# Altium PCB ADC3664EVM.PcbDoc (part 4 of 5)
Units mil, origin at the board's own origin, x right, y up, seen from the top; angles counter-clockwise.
Board outline 3900 x 2716.54 mil, 10 copper layers (Top Layer, L2 GND, L3 PWR, L4 GND, L5 SIG, L6 GND, L7 GND, L8 PWR, L9 GND, Bottom Layer), stack 61.2 mil thick; 332 components, 223 nets, 1425 pads, 969 vias.
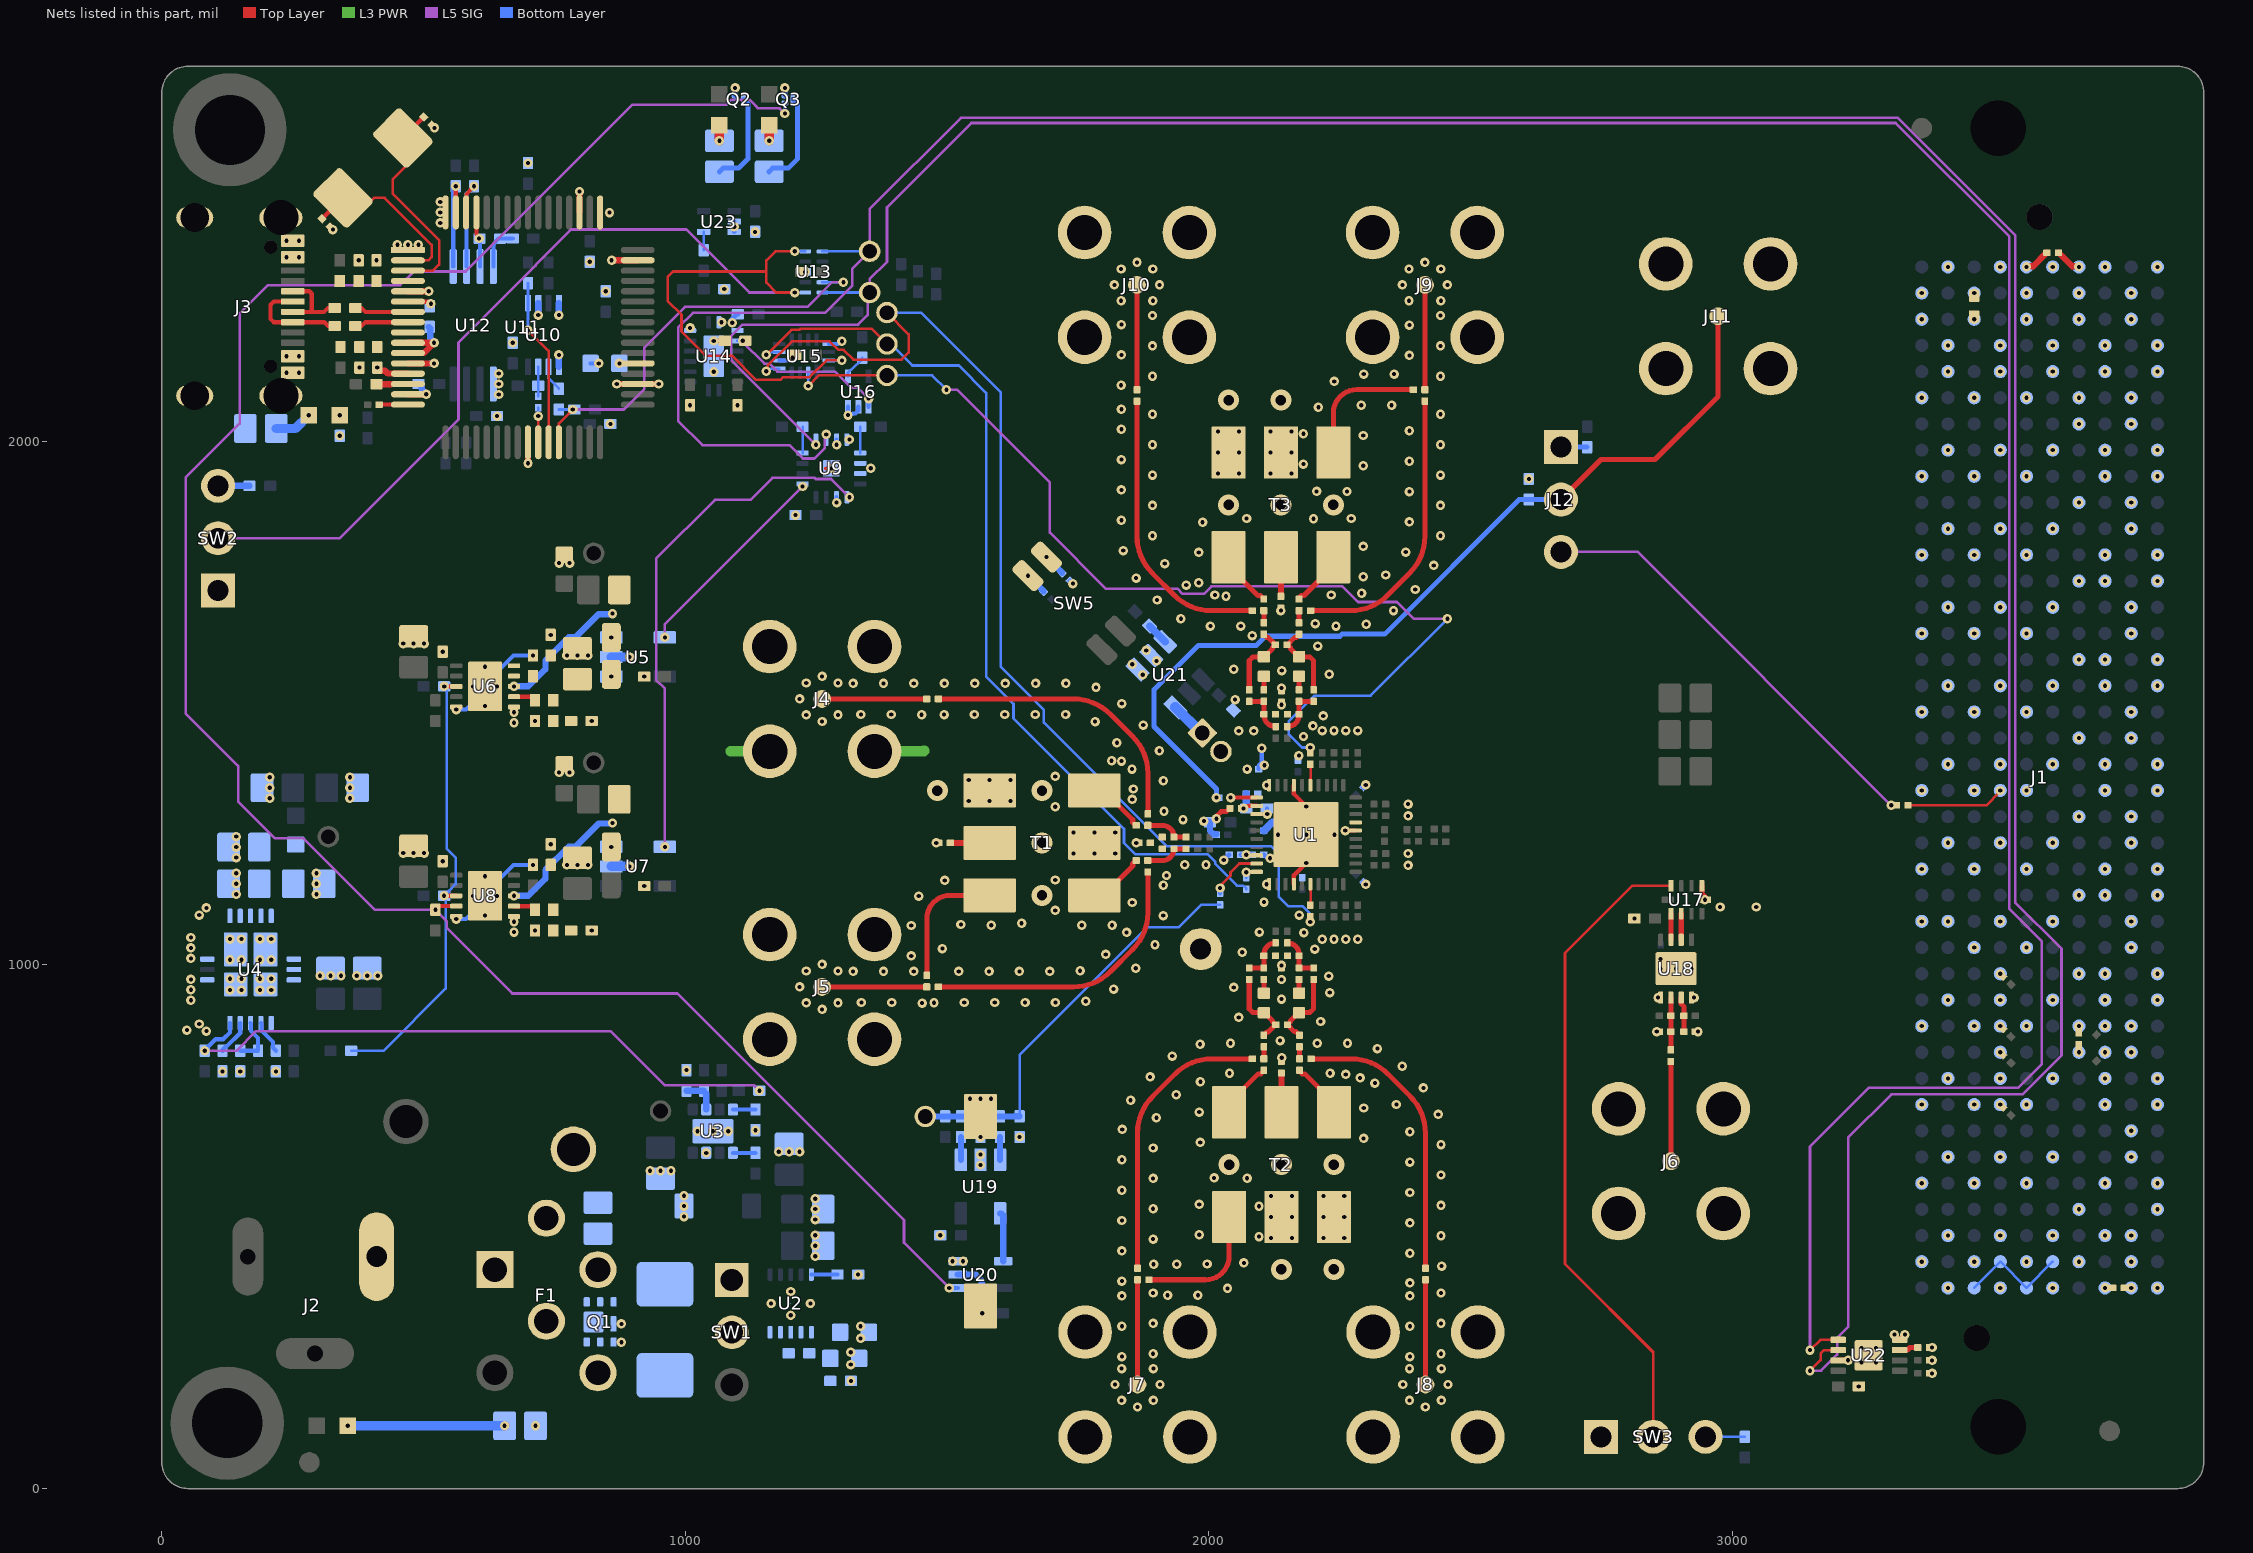
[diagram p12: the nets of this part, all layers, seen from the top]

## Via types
v1: diameter 18, hole 8, Top Layer to Bottom Layer, tented both sides, 952 vias
v2: diameter 40, hole 20, Top Layer to Bottom Layer, tented both sides, 14 vias
v3: diameter 18, hole 8, Top Layer to Bottom Layer, tented bottom, 3 vias

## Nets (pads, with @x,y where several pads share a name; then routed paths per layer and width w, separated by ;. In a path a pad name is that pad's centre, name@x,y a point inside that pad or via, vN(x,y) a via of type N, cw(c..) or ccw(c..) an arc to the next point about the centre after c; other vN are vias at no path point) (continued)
GND: C2.1 C3.1 C4.1 C5.1 C6.1 C7.1 C8.1 C9.1 C10.1 C11.1 C12.1 C13.1 C14.1 C15.1 C16.2 C17.1 C18.1 C19.1 C20.1 C21.1 C22.1 C23.1 C24.1 C25.1 C26.1 C27.1 C28.1 C29.1 C30.1 C31.1 C32.1 C33.1 C34.1 C35.1 C36.1 C37.1 C38.1 C39.1 C40.1 C41.1 C42.1 C43.1 C44.1 C45.1 C46.1 C47.1 C50.2 C51.1 C55.1 C56.1 C61.1 C62.2 C69.1 C70.2 C74.1 C75.1 C76.1 C77.1 C78.1 C79.1 C80.1 C81.1 C82.1 C83.1 C84.1 C85.1 C86.1 C87.1 C88.1 C89.1 D3.2 J1.A1 J1.A4 J1.A5 J1.A8 J1.A9 J1.A12 J1.A13 J1.A16 J1.A17 J1.A20 J1.A21 J1.A24 J1.A25 J1.A28 J1.A29 J1.A32 J1.A33 J1.A36 J1.A37 J1.A40 J1.B2 J1.B3 J1.B6 J1.B7 J1.B10 J1.B11 J1.B14 J1.B15 J1.B18 J1.B19 J1.B22 J1.B23 J1.B26 J1.B27 J1.B30 J1.B31 J1.B34 J1.B35 J1.B38 J1.B39 J1.C1 J1.C4 J1.C5 J1.C8 J1.C9 J1.C12 J1.C13 J1.C16 J1.C17 J1.C20 J1.C21 J1.C24 J1.C25 J1.C28 J1.C29 J1.C32 J1.C33 J1.C36 J1.C38 J1.C40 J1.D2 J1.D3 J1.D6 J1.D7 J1.D10 J1.D13 J1.D16 J1.D19 J1.D22 J1.D25 J1.D28 J1.D37 J1.D39 J1.E1 J1.E4 J1.E5 J1.E8 J1.E11 J1.E14 J1.E17 J1.E20 J1.E23 J1.E26 J1.E29 J1.E32 J1.E35 J1.E38 J1.E40 J1.F2 J1.F3 J1.F6 J1.F9 J1.F12 J1.F15 J1.F18 J1.F21 J1.F24 J1.F27 J1.F30 J1.F33 J1.F36 J1.F39 J1.G1 J1.G4 J1.G5 J1.G8 J1.G11 J1.G14 J1.G17 J1.G20 J1.G23 J1.G26 J1.G29 J1.G32 J1.G35 J1.G38 J1.G40 J1.H3 J1.H6 J1.H9 J1.H12 J1.H15 J1.H18 J1.H21 J1.H24 J1.H27 J1.H30 J1.H33 J1.H36 J1.H39 J1.J1 J1.J4 J1.J5 J1.J8 J1.J11 J1.J14 J1.J17 J1.J20 J1.J23 J1.J26 J1.J29 J1.J32 J1.J35 J1.J38 J1.J40 J1.K2 J1.K3 J1.K6 J1.K9 J1.K12 J1.K15 J1.K18 J1.K21 J1.K24 J1.K26 J1.K30 J1.K33 J1.K36 J1.K39 J3.1 J3.2 J3.3 J3.4 J3.A1 J3.B1 J4.2 J4.3 J4.4 J4.5 J5.2 J5.3 J5.4 J5.5 J6.2 J6.3 J6.4 J6.5 J7.2 J7.3 J7.4 J7.5 J8.2 J8.3 J8.4 J8.5 J9.2 J9.3 J9.4 J9.5 J10.2 J10.3 J10.4 J10.5 J11.2 J11.3 J11.4 J11.5 Q1.4 Q1.7 Q2.2@1095,2660 Q3.2@1190,2660 R2.1 R3.1 R4.1 R8.1 R13.1 R14.1 R20.1 R22.1 R29.1 R31.1 R45.1 R46.1 R55.1 R58.2 R73.1 R74.1 R106.1 R125.1 R132.1 R133.1 R134.1 R135.1 R136.1 R137.1 R146.1 R147.1 R150.2 SW2.3 SW3.3 SW4.2 T1.1 T1.5 T2.2 T2.3 T3.2 T3.3 U1.3 U1.11 U1.14 U1.26 U1.37 U1.40 U1.41 U2.11 U3.3 U3.9 U4.1 U4.2 U4.3 U4.5 U4.6 U4.7 U4.8 U4.9 U4.16 U4.17 U4.20 U4.25 U4.26 U4.28 U5.2 U6.6 U6.11 U7.2 U8.6 U8.11 U9.2 U9.3 U9.6 U9.15 U9.16 U9.17 U10.2 U10.4 U10.5 U11.1 U11.5 U11.10 U11.11 U11.13 U11.15 U11.25 U11.35 U11.47 U11.51 U12.5 U13.3@1228.98,2323.6 U14.7 U14.9 U14.10 U14.17 U15.6 U15.13 U16.2 U16.3 U17.5 U17.6 U18.1 U18.4 U18.9 U19.2 U20.3 U21.1 U21.2 U22.4 U22.7 U22.9 U23.2 U23.3 | length 1947.6
  Top Layer w8: v1(460.98,1213.72) 474.98,1227.72 C24.1@480.98,1227.72 ; v1(460.98,1613.72) 474.98,1627.72 C18.1@480.98,1627.72 ; v1(480.98,1213.72) C24.1@480.98,1227.72 ; v1(480.98,1613.72) C18.1@480.98,1627.72 ; v1(500.98,1213.72) 486.98,1227.72 C24.1@480.98,1227.72 ; v1(500.98,1613.72) 486.98,1627.72 C18.1@480.98,1627.72 ; v1(758.74,1367.62) 758.74,1373.36 C27.1@768.74,1383.36 778.74,1373.36 v1(778.74,1367.62) ; v1(758.74,1767.62) 758.74,1773.36 C21.1@768.74,1783.36 778.74,1773.36 v1(778.74,1767.62) ; v1(773.72,1191.03) 787.72,1205.03 C26.1@793.72,1205.03 ; v1(773.72,1591.03) 787.72,1605.03 C20.1@793.72,1605.03 ; v1(793.72,1191.03) C26.1@793.72,1205.03 ; v1(793.72,1591.03) C20.1@793.72,1605.03 ; v1(813.72,1191.03) 799.72,1205.03 C26.1@793.72,1205.03 ; v1(813.72,1591.03) 799.72,1605.03 C20.1@793.72,1605.03 ; v1(1479.06,1233.05) C50.2@1484.06,1233.05 ; v1(1861.06,1233.05) C51.1@1866.06,1233.05 ; U1.3@2091.2,1288.17 v1(2111.2,1288.17) ; v1(2109.82,1154.31) U1.11@2114.82,1154.31 ; v1(2109.82,1343.29) U1.40@2114.82,1343.29 ; v1(2137.46,1676.83) C70.2@2137.46,1681.83 ; C69.1@2138.45,1523.99 v1(2138.45,1528.99) ; U1.14@2162.07,1154.31 2162.07,1171.24 U1.41@2185.69,1194.86 ; U1.37@2162.07,1343.29 2162.07,1326.36 U1.41@2185.69,1302.73 ; v1(2260.18,1256.67) U1.26@2280.18,1256.67 ; v1(2857.58,937.74) U18.1@2862.58,937.74 ; U18.4@2921.64,937.74 v1(2926.64,937.74) ; 1269.05,1948.3 U9.17@1278.9,1948.29 1269.05,1948.29
  Top Layer w9: U14.17@1054.25,2192.04 R55.1@1075.16,2192.04 ; v1@2015,1285 2022.99,1292.99 2033.44,1292.99 2039.37,1298.92 C85.1@2040.16,1298.92
  Top Layer w9.7: U17.6@2941.32,1151.13 2941.32,1136.36 2947.23,1130.46 v1(2947.23,1124.55)
  Top Layer w10: U22.7@3201.8,244.68 3202.01,244.88 3220.36,244.88 v1(3220.57,245.09) ; v1(3309.06,294.05) U22.4@3319.06,284.05 v1(3329.06,294.05) ; R134.1@3376.1,219.99 v1(3381.1,219.99) ; R135.1@3376.1,244.68 v1(3381.1,244.68) ; R136.1@3376.1,269.36 v1(3381.1,269.36) ; v1(3461.42,2233.27) R146.1@3461.42,2238.58 ; v1(3711.42,383.27) R137.1@3726.08,383.27
  Top Layer w12: C42.1@321.7,2409.56 v1(326.7,2404.56) ; v1(411.37,2140.87) 411.37,2138.91 415.21,2135.06 426.33,2135.06 431.82,2129.57 469.65,2129.57 U11.13@470,2129.23 ; U11.15@470,2089.86 v1(505,2089.86) ; U11.11@470,2168.6 500.32,2168.6 v1(520,2188.28) U11.10@470,2188.28 ; U11.5@470,2286.71 v1(510,2286.71) ; C43.1@515.84,2603.7 v1(520.84,2598.7) ; v1(699.33,1958.32) U11.25@699.33,1998.32 ; U11.51@797.76,2437.3 v1(797.76,2477.3) ; v1(858.98,2345.76) U11.47@908.98,2345.76 ; v1(868.98,2109.54) U11.35@908.98,2109.54 v1(948.98,2109.54)
  L3 PWR w20: 1086.21,1408.05 J4.4@1161.11,1408.05 ; J4.5@1361.11,1408.05 1454.85,1408.05 1455.97,1409.17
  Bottom Layer w5: U14.7@1008.98,2211.73 v1(1008.98,2216.73) ; U14.9@1064.09,2227.47 v1(1069.09,2227.47)
  Bottom Layer w8: C35.1@818.86,2148.91 v1(834.61,2148.91) ; U23.3@1093.18,2400.12 v1(1093.18,2409.96) U23.2@1093.18,2419.8 ; U15.6@1179.53,2154.64 1196.82,2154.64 1201.82,2159.64 v1(1204.53,2159.64) ; U15.13@1274.02,2186.14 1291.31,2186.14 1296.31,2191.14 v1(1299.02,2191.14) ; v1(1288.74,1883.18) U9.6@1288.74,1893.18 ; v1(1288.74,1993.41) U9.15@1288.74,2003.41 ; U16.3@1310.63,2065.97 1310.63,2052.78 v1(1310.63,2050.22) 1312.54,2052.13 1319.1,2052.13 1320.32,2053.35 1324.98,2053.35 1330.32,2058.68 U16.2@1330.32,2065.97 ; v1(2028.18,1200.25) 2028.18,1200.67 2037.94,1210.43 C79.1@2038.72,1210.43 ; R132.1@2094.77,1374.15 2094.77,1380.45 2100.76,1386.44 v1(2100.76,1413.81) ; C80.1@2104.53,1210.43 2105.32,1210.43 2111.25,1204.5 2116.05,1204.5 v1(2116.62,1203.93) ; C83.1@2110.57,1298.92 2110.57,1289.07 2111.2,1289.07 v1(2111.2,1288.17)
  Bottom Layer w9: v1(1089.53,2226.73) 1089.05,2227.2 1089.05,2233.76 1098.32,2243.02 R58.2@1100.29,2243.02
  Bottom Layer w9.7: Q2.2@1095,2660 v1(1095,2675) ; Q3.2@1190,2660 v1(1190,2675) ; R133.1@1735.07,1733.29 v1(1740.07,1728.29)
  Bottom Layer w12: C37.1@490.24,2109.54 492.21,2109.54 496.06,2105.7 496.06,2099.89 505,2090.94 v1(505,2089.86) ; R46.1@510,2218.61 512.81,2215.81 512.81,2197.1 520,2189.9 v1(520,2188.28) v1@512,2188.28 ; v1(719.02,2241.27) U10.2@719.02,2264.27 ; U10.5@758.39,2142.22 v1(758.39,2165.22) ; v1(758.39,2241.27) U10.4@758.39,2264.27 ; v1@1313.15,2002.7 v1(1313.15,2003.55) ; v1(1990.19,1274.7) 1991.33,1273.56 2000.69,1273.56 C87.1@2001.83,1272.42 2001.83,1256.45 2008.86,1249.42 C88.1@2014.16,1249.42 ; C77.1@2295.77,1157.34 v1(2299.3,1153.81) ; C78.1@2295.77,1340.25 v1(2299.3,1343.79)
  Bottom Layer w15: C75.1@2104.53,1256.67 2105.32,1256.67 2121.07,1272.42 2126.64,1272.42
  Bottom Layer w18: U7.2@858.46,1188.15 v1(893.46,1188.15) ; U5.2@858.46,1588.15 v1(893.46,1588.15)
  other v1: 713.73,119.85 1863.45,155.72 2413.45,155.72 1833.04,168.31 1893.85,168.31 2383.04,168.31 2443.85,168.31 3241.17,194.99 1820.45,198.72 1906.45,198.72 2370.45,198.72 2456.45,198.72 1316.31,205.62 1833.04,229.13 1893.85,229.13 2383.04,229.13 2443.85,229.13 1315.9,236.67 1833.73,251.91 2383.73,251.91 1893.17,257.52 2443.17,257.52 1315.9,260.14 877.82,279.42 1334.68,286.67 1334.68,310.14 1833.73,309.91 2383.73,309.91 877.82,314.42 1893.17,315.52 2443.17,315.52 1833.73,367.91 2383.73,367.91 1920.88,369 1978.88,369 1893.17,373.52 2443.17,373.52 2035.36,382.2 3411.42,383.27 3511.42,383.27 3611.42,383.27 3811.42,383.27 2383.73,392.76 1833.72,396.3 1329.96,408.64 2444.32,424.84 1894.32,428.42 1938.51,428.44 1996.5,428.81 2066.73,430.98 3361.42,433.27 3461.42,433.27 3561.42,433.27 3661.42,433.27 3761.42,433.27 1510.3,434.23 1530.3,434.23 1248.09,443.64 2383.73,449.44 1833.73,453.87 1248.09,463.64 1893.17,476.41 2118.45,478.72 2158.45,478.72 2218.45,478.72 2258.45,478.72 2095.58,481.3 2443.17,482.83 1248.09,483.64 1486.89,483.65 3411.42,483.27 3511.42,483.27 3611.42,483.27 3711.42,483.27 3761.42,483.27 1981.32,484.79 2383.73,507.44 1833.73,511.87 1248.09,513.64 2118.45,518.72 2158.45,518.72 2218.45,518.72 2258.45,518.72 997.3,519.36 1248.09,533.64 3661.42,533.27 3811.42,533.27 1893.17,534.41 997.3,539.36 2095.58,539.3 2443.17,540.83 1981.32,542.79 1248.09,553.64 2118.45,558.72 2158.45,558.72 2218.45,558.72 2258.45,558.72 997.3,559.36 2383.73,565.44 1833.73,569.87 3361.42,583.27 3461.42,583.27 3561.42,583.27 3711.42,583.27 3811.42,583.27 1893.17,592.41 2072.72,592.61 2009.73,593.35 2443.17,598.83 932.5,606.94 952.5,606.94 972.5,606.94 1563.61,617.87 2383.73,623.44 1833.73,627.87 3411.42,633.27 3511.42,633.27 3611.42,633.27 3761.42,633.27 1563.61,637.87 1039.7,641.15 1178.13,643.42 1198.13,643.42 1218.13,643.42 1893.17,650.41 2443.17,656.83 1983.29,661.04 2295.21,668.82 1563.61,671.34 1638.32,671.43 2383.69,681.44 3761.42,683.27 1133.88,684.46 1834.29,685.87 1899.57,708.05 2437.83,714.58 1981.32,719.01 2295.58,726.82 2358.06,733.47 3361.42,733.27 3461.42,733.27 3561.42,733.27 3711.42,733.27 3811.42,733.27 1850.33,741.61 1543.61,744.61 1563.61,744.61 1583.61,744.61 1937.39,752.02 2409.59,765.24 2316.86,774.3 1983.52,776.97 3411.42,783.27 3511.42,783.27 3611.42,783.27 3711.42,783.27 3811.42,783.27 2288.58,784.39 1887.47,786.16 2261.33,791.05 2039.16,793.35 2231.27,793.35 115.89,796.75 149.89,796.75 217.89,796.75 1002.1,799.2 2368.96,806.63 2138.87,822.85 1929.7,825.92 3761.42,833.27 2321.72,840.29 1983.09,848.57 2041.06,850.49 2206.62,850.49 2264.62,850.49 2135.87,855.52 2855.22,872.74 2934,872.74 85.27,873.58 47.89,875.49 3361.42,883.27 3461.42,883.27 3561.42,883.27 3761.42,883.27 71.55,887.3 2213.26,892 2056.72,899.9 1261.11,915.05 1230.7,927.64 1291.51,927.64 1452.07,927.18 1474.77,927.69 1336.09,928.33 1394.09,928.33 1532.76,928.33 1590.76,928.33 1648.76,928.33 1706.76,928.33 1764.71,930.73 55.51,932.48 3411.42,933.27 3511.42,933.27 3611.42,933.27 3711.42,933.27 3811.42,933.27 2138.45,934.79 2230.67,947.33 55.51,952.48 1817.9,953.86 2047.21,957.11 1218.11,958.05 55.51,972.48 2138.45,972.22 2228.88,978.84 302.26,979.25 322.26,979.25 342.26,979.25 372.26,979.25 392.26,979.25 412.26,979.25 3661.42,983.27 3711.42,983.27 3811.42,983.27 1320.3,987.77 1378.3,987.77 1436.3,987.77 1521.96,987.77 1579.96,987.77 1637.96,987.77 1695.96,987.77 1230.7,988.46 1291.51,988.46 1753.95,988.8 1860.11,993.63 1261.11,1001.05 2862.58,1011.37 55.51,1012.48 1431.39,1017.35 1802.68,1020.26 2063.68,1024.29 2202.05,1030.26 1490.83,1031.32 55.51,1032.48 3461.42,1033.27 3561.42,1033.27 3761.42,1033.27 1896.97,1038.42 2216.16,1049.26 2238.76,1049.26 2261.36,1049.26 2283.96,1049.26 55.51,1052.48 2181.3,1061.83 672.72,1062.68 1842.66,1062.28 2096.27,1062.84 712.72,1065.91 821.09,1065.91 1431.39,1075.35 1584.19,1075.92 1757.05,1075.92 1815.05,1075.92 1526.21,1077.28 1642.06,1079.77 672.72,1082.68 3361.42,1083.27 3411.42,1083.27 3511.42,1083.27 3611.42,1083.27 3761.42,1083.27 2812.41,1088.72 1912.59,1094.28 71.55,1095.3 2172.52,1095.34 1706.48,1104.31 85.27,1109.02 2976.29,1110.64 3045.39,1110.64 1853.44,1119.27 2105.13,1120.16 1445.8,1131.53 3661.42,1133.27 3711.42,1133.27 3811.42,1133.27 142.26,1135 295.33,1135 921.46,1150.75 1912.87,1152.28 142.26,1155 295.33,1155 1495.39,1161.6 1706.48,1162.31 1918.93,1170.82 142.26,1175 295.33,1175 3361.42,1183.27 3461.42,1183.27 3561.42,1183.27 3711.42,1183.27 3811.42,1183.27 2380.23,1190.25 1953.79,1191.31 1994.38,1191.25 536.41,1198.19 142.26,1205.06 2380.23,1212.85 1741.11,1213.05 1781.11,1213.05 1821.11,1213.05 142.26,1225.06 742.72,1230.47 3411.42,1233.27 3511.42,1233.27 3611.42,1233.27 3761.42,1233.27 142.26,1245.06 1741.11,1253.05 1781.11,1253.05 1821.11,1253.05 1950.39,1277.59 2014.22,1279.37 3661.42,1283.27 3761.42,1283.27 2380.23,1284.74 1914.03,1293.68 1706.56,1302.08 2380.23,1307.34 1541.11,1313.05 1581.11,1313.05 1621.11,1313.05 1853.44,1316.16 206.27,1318.49 359.34,1318.49 3361.42,1333.27 3461.42,1333.27 3561.42,1333.27 3711.42,1333.27 3811.42,1333.27 1855.74,1336.13 206.27,1338.49 359.34,1338.49 1912.87,1351.66 1541.11,1353.05 1581.11,1353.05 1621.11,1353.05 206.27,1358.49 359.34,1358.49 1706.48,1360.08 1852.93,1374.15 2105.95,1381.33 3411.42,1383.27 3511.42,1383.27 3611.42,1383.27 3711.42,1383.27 3811.42,1383.27 1832.88,1389.44 1814.05,1390.18 2171.78,1399.92 1905.33,1409.17 1824.06,1424.46 3661.42,1433.27 3761.42,1433.27 2180.47,1436.31 2056.72,1446.94 2085.6,1447.04 2216.16,1447.62 2238.76,1447.62 2261.36,1447.62 2283.96,1447.62 2198.41,1456.49 1874.37,1458.21 672.72,1462.68 1782.46,1464.87 1261.11,1465.05 712.72,1465.91 821.09,1465.91 2218.11,1475.79 1230.7,1477.64 1291.51,1477.64 1335.23,1478.33 1393.23,1478.33 1451.23,1477.98 1494.04,1478.18 1552.04,1478.33 1610.04,1478.33 1668.04,1478.33 1726.04,1478.33 672.72,1482.68 3361.42,1483.27 3461.42,1483.27 3561.42,1483.27 3761.42,1483.27 1833.35,1499.23 2049.89,1506.87 1218.11,1508.05 1784.28,1530.13 3411.42,1533.27 3511.42,1533.27 3611.42,1533.27 3711.42,1533.27 3811.42,1533.27 1320.3,1537.77 1378.3,1537.77 1436.3,1537.77 1494.78,1537.77 1552.78,1537.77 1610.78,1537.77 1668.78,1537.77 1726.78,1537.77 1230.7,1538.46 1291.51,1538.46 921.46,1550.75 1261.11,1551.05 1873.6,1554.26 2229.69,1555.16 2139.08,1562.22 2047.21,1564.81 1853.6,1574.26 1900.05,1580.71 3661.42,1583.27 3711.42,1583.27 3811.42,1583.27 536.41,1598.19 1880.05,1600.71 2207.91,1608.91 2082.49,1629.16 742.72,1630.47 3361.42,1633.27 3461.42,1633.27 3561.42,1633.27 3761.42,1633.27 2002.77,1647.21 2060.77,1647.11 2242.62,1647.11 2300.51,1650.68 2202.84,1652 1946.45,1661.08 2352.34,1676.71 3411.42,1683.27 3511.42,1683.27 3611.42,1683.27 3761.42,1683.27 1900.91,1697 2032.53,1704.24 2011.27,1706.55 2233.6,1706.55 2291.51,1709.75 2394.04,1717.03 1956.43,1725.44 1980.51,1729.9 3661.42,1733.27 3711.42,1733.27 3811.42,1733.27 1860.76,1738.86 2294.59,1741.46 2337.73,1744.79 2429.31,1763.07 1915.47,1766.51 3361.42,1783.27 3461.42,1783.27 3561.42,1783.27 3711.42,1783.27 3811.42,1783.27 1980.33,1787.9 2375.81,1788.54 1836.08,1791.35 2294.59,1799.46 1892.18,1819.62 2442.18,1819.62 3411.42,1833.27 3511.42,1833.27 3611.42,1833.27 3761.42,1833.27 1987.91,1845.41 2382.74,1846.12 1832.74,1849.25 2071.74,1852.77 2199.55,1852.04 2271.74,1852.77 1210.26,1859.23 1892.18,1877.62 2442.18,1877.62 3661.42,1883.27 3761.42,1883.27 2205.63,1904.5 2263.63,1904.24 2382.74,1904.12 1832.74,1907.25 2610.97,1928.25 3361.42,1933.27 3461.42,1933.27 3561.42,1933.27 3711.42,1933.27 3811.42,1933.27 1892.18,1935.62 2442.18,1935.62 2017.46,1938.88 2057.46,1938.88 2117.46,1938.88 2157.46,1938.88 1354.11,1948.52 2294.59,1953.29 2180.33,1956.69 2382.74,1962.12 1832.74,1965.25 2017.46,1978.88 2057.46,1978.88 2117.46,1978.88 2157.46,1978.88 3411.42,1983.27 3511.42,1983.27 3611.42,1983.27 3711.42,1983.27 3811.42,1983.27 1892.18,1993.62 2442.18,1993.62 340,2010.63 2294.59,2011.29 2180.33,2014.69 2017.46,2018.88 2057.46,2018.88 2117.46,2018.88 2157.46,2018.88 2382.74,2020.12 1832.74,2023.25 856.81,2033.32 3661.42,2033.27 3761.42,2033.27 640.28,2048.32 1892.18,2051.62 2442.18,2051.62 1832.74,2061.25 2208.98,2065.12 1008.98,2068.93 1099.53,2068.93 2290.7,2069.16 2348.7,2069.16 3361.42,2083.27 3461.42,2083.27 3561.42,2083.27 3661.42,2083.27 3761.42,2083.27 643.39,2089.54 1832.07,2107.12 643.39,2109.54 2239.4,2114.51 1892.18,2124.43 2442.18,2124.43 2295.66,2128.6 2353.66,2128.6 643.39,2129.54 238.16,2131.19 262.16,2131.19 3411.42,2133.27 3511.42,2133.27 3611.42,2133.27 3711.42,2133.27 3811.42,2133.27 377.37,2140.87 2382.74,2164.14 1832.74,2165.11 1892.18,2182.43 2442.18,2182.43 3411.42,2183.27 3511.42,2183.27 3611.42,2183.27 3711.42,2183.27 3811.42,2183.27 670.29,2188.28 2382.74,2222.14 1832.74,2223.11 3361.42,2233.27 3561.42,2233.27 3661.42,2233.27 3761.42,2233.27 1892.18,2240.43 2442.18,2240.43 1832.06,2268.47 1892.87,2268.47 2382.06,2268.47 2442.87,2268.47 3361.42,2283.27 3561.42,2283.27 3661.42,2283.27 3761.42,2283.27 847.98,2286.71 1074.29,2290.74 1819.46,2298.88 1905.46,2298.88 2369.46,2298.88 2455.46,2298.88 1228.98,2323.6 1832.06,2329.28 1892.87,2329.28 2382.06,2329.28 2442.87,2329.28 3411.42,2333.27 3511.42,2333.27 3611.42,2333.27 3711.42,2333.27 3811.42,2333.27 1862.46,2341.88 2412.46,2341.88 817.44,2342.93 376,2345.76 410,2345.76 450,2375.45 470,2375.45 490,2375.45 238.16,2383.16 262.16,2383.16 1133.18,2400.12 699.33,2531.67
  other v2: 2138.45,418.72 2238.45,418.72 2038.45,618.72 2138.45,618.72 2238.45,618.72 1681.11,1133.05 1681.11,1233.05 1481.11,1333.05 1681.11,1333.05 2037.46,1878.88 2137.46,1878.88 2237.46,1878.88 2037.46,2078.88 2137.46,2078.88
IOVDD_PG: Q3.1@1190,2646.22 R24.1 U8.4 U20.1 | length 4093
  Top Layer w8: v1(522.48,1105.28) 522.48,1106.52 528.32,1112.36 U8.4@562.48,1112.36
  L5 SIG w5: 898.37,2642.72 580.14,2324.49 481.52,2324.49 455.32,2298.29 202.71,2298.29 148.81,2244.39 148.81,2034.01 45.51,1930.7 45.51,1480.61 145.67,1380.45 145.67,1312.5 216.33,1241.84 270.16,1241.84 406.73,1105.28 v1(522.48,1105.28) 544.38,1083.37 544.38,1070.5 669.37,945.51 984.64,945.51 1417.41,512.74 1417.41,469.72 v1(1504.08,383.05) ; 898.7,2643.05 1078.5,2643.05 1088.17,2652.72 1122.01,2652.72 1134.61,2640.12 1138.51,2636.22 1180,2636.22 v1(1190,2626.22)
  Bottom Layer w8: v1(1190,2626.22) Q3.1@1190,2646.22 ; v1(1504.08,383.05) U20.1@1520.3,383.05
ISENSE_AVDD: U5.4 U9.9 | length 402.1
  L5 SIG w5: v1(960.83,1625.55) 960.83,1650.82 v1(1223.78,1913.77)
  Bottom Layer w5: v1(1223.78,1913.77) U9.9@1223.78,1918.77
ISENSE_IOVDD: U7.4 U9.5 | length 1011
  L5 SIG w5: v1(960.83,1225.55) 960.83,1527.72 944.33,1544.22 944.33,1776.67 1056.16,1888.5 1124.47,1888.5 1166.24,1930.27 1246.64,1930.27 1248.83,1928.07 1278.53,1928.07 v1(1313.42,1893.18)
  Bottom Layer w5: U9.5@1308.42,1893.18 v1(1313.42,1893.18)
NetC1_1: C1.1 D2.2 F1.2 Q1.3 SW1.1
NetC1_2: C1.2 D2.1 F1.4 Q1.1 Q1.2 Q1.5 Q1.6 Q1.8
NetC4_2: C4.2 R1.1 R4.2 U2.2
NetC5_2: C5.2 U2.1
NetC8_2: C8.2 U3.8 | length 43
  Bottom Layer w8: U3.8@1090.88,723.83 C8.2@1133.88,723.83
NetC11_2: C11.2 C12.2 C13.2 FB1.1 U4.10 U4.11 U4.12 U4.13 U4.14 U4.15 U4.27
NetC16_1: C16.1 U4.21 | length 64.7
  Bottom Layer w8: U4.21@189.27,888.94 190.19,888.02 190.19,874.88 212.1,852.96 212.1,841.91 C16.1@217.89,836.12
NetC20_2: C20.2 R17.1 R19.2 U5.1 U6.9 U6.10
  other v1: 858.46,1550.75
NetC22_2: C22.2 R21.2 U6.7 | length 44
  Top Layer w9: U6.7@672.72,1512.36 707.37,1512.36 712.72,1507.02 C22.2@712.72,1505.28
NetC28_2: C28.2 R30.2 U8.7 | length 44
  Top Layer w9: U8.7@672.72,1112.36 707.37,1112.36 712.72,1107.02 C28.2@712.72,1105.28
NetC31_2: C31.2 C32.2 FB4.2 U11.9
NetC33_2: C33.2 C34.2 FB5.2 U11.4
NetC42_2: C42.2 U11.2 Y1.1 | length 338.6
  Top Layer w5: Y1.1@346.11,2465.15 351.11,2460.15 400.47,2460.15 405.47,2465.15 425.62,2465.15 515.29,2375.49 515.29,2351.67 509.38,2345.76 U11.2@470,2345.76
  Top Layer w8: C42.2@306.11,2425.15 Y1.1@346.11,2465.15
NetC43_2: C43.2 U11.3 Y1.2 | length 411.4
  Top Layer w5: Y1.2@460.25,2579.29 465.25,2574.29 465.25,2524.93 440.9,2500.58 440.9,2472.95 529.61,2384.23 529.61,2337.89 517.8,2326.08 U11.3@470,2326.08
  Top Layer w8: Y1.2@460.25,2579.29 C43.2@500.25,2619.29
NetC48_1: C48.1 C49.2 R62.2 R64.2 | length 85.7
  Top Layer w9.7: C49.2@1883.16,1266.57 1910.93,1266.57 cw(c1910.93,1244.35) R64.2@1933.16,1244.35 C48.1@1956.16,1244.35
NetC49_1: C49.1 T1.6 | length 110.3
  Top Layer w9.7: T1.6@1781.11,1333.05 1798.61,1333.05 1854.39,1277.27 1854.39,1272.5 1860.32,1266.57 C49.1@1861.11,1266.57
NetC50_1: C50.1 T1.2 | length 75
  Top Layer w12: C50.1@1506.11,1233.05 T1.2@1581.11,1233.05
NetC51_2: C51.2 R64.1 R66.2
NetC52_1: C52.1 T1.3 | length 253.6
  Top Layer w9.7: C52.1@1461.11,980.1 1461.11,1088.05 cw(c1506.11,1088.05) 1506.11,1133.05 T1.3@1581.11,1133.05
NetC53_1: C53.1 C54.1 R66.1 R68.2 | length 85.7
  Top Layer w9.7: C53.1@1883.16,1199.53 1910.93,1199.53 ccw(c1910.93,1221.75) R66.1@1933.16,1221.75 C54.1@1956.16,1221.75
NetC53_2: C53.2 T1.4 | length 110.3
  Top Layer w9.7: T1.4@1781.11,1133.05 1798.61,1133.05 1854.39,1188.83 1854.39,1193.6 1860.32,1199.53 C53.2@1861.11,1199.53
NetC57_1: C57.1 R70.1 R74.2 U18.2 | length 100
  Top Layer w9.7: C57.1@2882.27,837.74 R74.2@2882.27,872.74 R70.1@2882.27,902.74 U18.2@2882.27,937.74
NetC57_2: C57.2 J6.1 | length 190.4
  Top Layer w9.7: J6.1@2882.27,625.27 2882.27,808.61 C57.2@2882.27,815.69
NetC58_1: C58.1 C59.1 J7.1 | length 200
  Top Layer w9.7: J7.1@1863.45,198.72 C58.1@1863.45,398.72
NetC58_2: C58.2 R76.1 | length 551.9
  Top Layer w9.7: C58.2@1863.45,420.77 1863.45,678.69 cw(c1963.45,678.69) 1892.74,749.4 1935.34,792 cw(c2004.78,722.56) 2004.78,820.77 R76.1@2082.88,820.77
NetC59_2: C59.2 T2.1 | length 253.6
  Top Layer w9.7: C59.2@1885.49,398.72 1993.45,398.72 ccw(c1993.45,443.72) 2038.45,443.72 T2.1@2038.45,518.72
NetC60_1: C60.1 T2.6 | length 110.3
  Top Layer w9.7: T2.6@2038.45,718.72 2038.45,736.22 2094.23,792 2098.99,792 2104.93,797.93 C60.1@2104.93,798.72
NetC60_2: C60.2 R76.2 R77.1 | length 23
  Top Layer w9.7: C60.2@2104.93,820.77 R77.1@2104.93,843.77
NetC62_1: C62.1 T2.5 | length 75
  Top Layer w12: T2.5@2138.45,718.72 C62.1@2138.45,793.72
NetC63_1: C63.1 L2.1 R85.2 R86.1 | length 150.7
  Top Layer w9.7: C63.1@2148.97,885.81 C63.1@2149.76,885.81 ; R85.2@2171.97,865.81 2171.97,866.6 2166.04,872.53 2163.04,872.53 C63.1@2149.76,885.81 ; R86.1@2199.97,971.43 2199.97,916.45 2192.65,909.13 2172.29,909.13 L2.1@2171.97,908.81 2170.98,908.81 2155.69,893.52 2155.69,891.74 C63.1@2149.76,885.81
NetC63_2: C63.2 L1.1 R77.2 R78.1 | length 150.7
  Top Layer w9.7: R78.1@2076.93,971.2 2076.93,916.22 2084.25,908.9 2104.61,908.9 2104.93,908.58 2105.91,908.58 2121.21,893.28 2121.21,891.51 C63.2@2127.14,885.58 ; R77.2@2104.93,865.58 2104.93,866.37 2110.86,872.3 2113.86,872.3 C63.2@2127.14,885.58 ; C63.2@2127.93,885.58 C63.2@2127.14,885.58
NetC64_1: C64.1 R84.2 R85.1 | length 23
  Top Layer w9.7: C64.1@2172.95,820.77 R85.1@2172.95,843.77
NetC64_2: C64.2 T2.4 | length 110.3
  Top Layer w9.7: C64.2@2171.97,798.72 2171.97,797.93 2177.9,792 2182.66,792 2238.45,736.22 T2.4@2238.45,718.72
NetC65_1: C65.1 J8.1 | length 200
  Top Layer w9.7: J8.1@2413.45,198.72 C65.1@2413.45,398.72
NetC65_2: C65.2 R84.1 | length 551.9
  Top Layer w9.7: R84.1@2194.02,820.77 2272.11,820.77 cw(c2272.11,722.56) 2341.56,792 2384.16,749.4 cw(c2313.45,678.69) 2413.45,678.69 C65.2@2413.45,420.77
NetC66_1: C66.1 C67.1 J9.1 | length 200
  Top Layer w9.7: C66.1@2412.46,2098.88 J9.1@2412.46,2298.88
NetC66_2: C66.2 R88.1 | length 551.9
  Top Layer w9.7: R88.1@2193.03,1676.83 2271.13,1676.83 ccw(c2271.13,1775.04) 2340.57,1705.59 2383.17,1748.19 ccw(c2312.46,1818.9) 2412.46,1818.9 C66.2@2412.46,2076.83
NetC67_2: C67.2 T3.1 | length 253.6
  Top Layer w9.7: T3.1@2237.46,1978.88 2237.46,2053.88 cw(c2282.46,2053.88) 2282.46,2098.88 C67.2@2390.42,2098.88
NetC68_1: C68.1 T3.6 | length 110.3
  Top Layer w9.7: C68.1@2170.98,1698.88 2170.98,1699.66 2176.91,1705.59 2181.68,1705.59 2237.46,1761.38 T3.6@2237.46,1778.88
NetC68_2: C68.2 R88.2 R89.1 | length 23
  Top Layer w9.7: R89.1@2171.97,1653.83 C68.2@2171.97,1676.83
NetC70_1: C70.1 T3.5 | length 75
  Top Layer w12: C70.1@2137.46,1703.88 T3.5@2137.46,1778.88
NetC71_1: C71.1 L4.1 R97.2 R98.1 | length 150.7
  Top Layer w9.7: R98.1@2076.93,1526.17 2076.93,1581.14 2084.25,1588.46 2104.61,1588.46 L4.1@2104.93,1588.78 2105.91,1588.78 2121.21,1604.08 2121.21,1605.85 C71.1@2127.14,1611.78 ; R97.2@2104.93,1631.78 2104.93,1630.99 2110.86,1625.06 2113.86,1625.06 C71.1@2127.14,1611.78 ; C71.1@2127.93,1611.78 C71.1@2127.14,1611.78
NetC71_2: C71.2 L3.1 R89.2 R90.1 | length 150.7
  Top Layer w9.7: C71.2@2148.97,1611.78 C71.2@2149.76,1611.78 ; R89.2@2171.97,1631.78 2171.97,1630.99 2166.04,1625.06 2163.04,1625.06 C71.2@2149.76,1611.78 ; R90.1@2199.97,1526.17 2199.97,1581.14 2192.65,1588.46 2172.29,1588.46 L3.1@2171.97,1588.78 2170.98,1588.78 2155.69,1604.08 2155.69,1605.85 C71.2@2149.76,1611.78
NetC72_1: C72.1 R96.2 R97.1 | length 23
  Top Layer w9.7: R97.1@2104.93,1653.83 C72.1@2104.93,1676.83
NetC72_2: C72.2 T3.4 | length 110.3
  Top Layer w9.7: T3.4@2037.46,1778.88 2037.46,1761.38 2093.24,1705.59 2098.01,1705.59 2103.94,1699.66 C72.2@2103.94,1698.88
NetC73_1: C73.1 J10.1 | length 200
  Top Layer w9.7: C73.1@1862.46,2098.88 J10.1@1862.46,2298.88
NetC73_2: C73.2 R96.1 | length 551.9
  Top Layer w9.7: C73.2@1862.46,2076.83 1862.46,1818.9 ccw(c1962.46,1818.9) 1891.75,1748.19 1934.35,1705.59 ccw(c2003.8,1775.04) 2003.8,1676.83 R96.1@2081.89,1676.83
NetD1_2: D1.2 R3.2 | length 300
  Bottom Layer w18: v1(355,120) R3.2@655,120
  other v1: 654.67,119.85
NetD4_2: D4.2 R18.2 | length 30
  Top Layer w18: v1(1065,2574.06) D4.2@1065,2604.06
NetD5_2: D5.2 R25.2 | length 30
  Top Layer w18: v1(1160,2574.06) D5.2@1160,2604.06
NetD6_2: D6.2 R45.2
  other v1: 340,2050
NetF1_1: F1.1 J2.1 TP1.1
NetFB2_1: FB2.1 R17.2 U5.3 U6.8 | length 255.5
  Bottom Layer w12: v1(672.65,1532.05) 700.02,1532.05 732.72,1564.76 732.72,1581.32 777.41,1626.01 790.09,1626.01 834.05,1669.98 859.68,1669.98 v1(860.83,1671.12)
  other v1: 858.46,1625.55
NetFB3_1: FB3.1 R27.2 U7.3 U8.8 | length 255.5
  Bottom Layer w12: v1(672.65,1132.05) 700.02,1132.05 732.72,1164.76 732.72,1181.32 777.41,1226.01 790.09,1226.01 834.05,1269.98 859.68,1269.98 v1(860.83,1271.12)
  other v1: 858.46,1225.55
NetJ1_B40: J1.B40 R137.2 | length 13.3
  Top Layer w10: R137.2@3748.13,383.27 v1(3761.42,383.27)
NetJ1_G21: J1.G21 R142.2 | length 185.4
  Top Layer w5: R142.2@3335,1305 3485,1305 v1@3510,1330
  other v1: 3511.42,1333.27
NetJ1_G28: J1.G28 R143.2 | length 6.7
  Top Layer w5: v1(3511.42,983.27) R143.2@3516.12,978.56
NetJ1_G30: J1.G30 R144.2 | length 6.7
  Top Layer w5: v1(3511.42,883.27) R144.2@3516.12,878.56
NetJ1_G31: J1.G31 R145.2 | length 6.7
  Top Layer w5: v1(3511.42,833.27) R145.2@3516.12,828.56
NetJ1_G33: J1.G33 R151.2 | length 6.7
  Top Layer w5: v1(3511.42,733.27) R151.2@3516.12,728.56
NetJ3_A4,B4: J3.A4 J3.B4 R42.1
  other v1: 238.16,2162.69 262.16,2162.69 238.16,2351.67 262.16,2351.67
NetJ3_A6: J3.A6 J3.B6 R44.1 | length 200
  Top Layer w8: J3.B6@245.62,2227.65 213.91,2227.65 207.83,2233.72 207.83,2260.95 213.91,2267.02 J3.A6@250.16,2267.02 ; J3.B6@245.63,2227.65 J3.B6@250.16,2227.65 310.15,2227.65 317.56,2220.25 R44.1@330.16,2220.25
NetJ3_A7: J3.A7 J3.B7 R43.1 | length 155.9
  Top Layer w8: J3.A7@250.16,2247.34 286.41,2247.34 ; J3.B7@250.16,2286.71 281.72,2286.71 286.41,2282.02 286.41,2247.34 ; R43.1@330.16,2254.74 317.32,2254.74 309.91,2247.34 286.41,2247.34
NetJ11_1: J11.1 J12.2 R106.2 R120.1 | length 1722.9
  Top Layer w9.7: J12.2@2672.25,1888.88 2748.62,1965.25 2851.97,1965.25 2972.46,2085.74 J11.1@2972.46,2238.88
  Bottom Layer w9.7: R120.1@2019.16,1319.66 v1(2014.16,1319.66) 2014.16,1336.14 1895,1455.29 1895,1525.59 1979.72,1610.3 2090.29,1610.3 2107.75,1627.76 2249.93,1627.76 2254,1631.83 2335.5,1631.83 2592.54,1888.88 J12.2@2672.25,1888.88
NetJ12_1: J12.1 R111.1 | length 50
  Bottom Layer w9.7: J12.1@2672.25,1988.88 R111.1@2722.25,1988.88
NetJ13_1: J13.1 U21.6 | length 71.6
  Bottom Layer w20: U21.6@1935.98,1491.88 1984.82,1443.04 J13.1@1987.4,1443.04
NetL1_2: L1.2 R80.1 | length 26
  Top Layer w9.7: L1.2@2104.93,946.22 R80.1@2104.93,972.22
NetL2_2: L2.2 R83.1 | length 26
  Top Layer w9.7: L2.2@2171.97,946.22 R83.1@2171.97,972.22
NetL3_2: L3.2 R92.1 | length 26
  Top Layer w9.7: R92.1@2171.97,1525.38 L3.2@2171.97,1551.38
NetL4_2: L4.2 R95.1 | length 26
  Top Layer w9.7: R95.1@2104.93,1525.38 L4.2@2104.93,1551.38
NetQ2_3: Q2.3 R18.1 | length 181.6
  Bottom Layer w9.7: R18.1@1065,2515 1071.82,2521.82 1101.43,2521.82 1119.42,2539.81 1119.42,2644.44 Q2.3@1110.75,2653.11
NetQ3_3: Q3.3 R25.1 | length 181.6
  Bottom Layer w9.7: R25.1@1160,2515 1166.82,2521.82 1196.43,2521.82 1214.42,2539.81 1214.42,2644.44 Q3.3@1205.75,2653.11
NetR1_2: R1.2 SW1.2 U2.3 U2.4 U2.5
NetR2_2: R2.2 U2.10 | length 50
  Bottom Layer w8: U2.10@1240.59,408.64 R2.2@1290.59,408.64
NetR6_1: R6.1 U3.1 | length 43
  Bottom Layer w8: U3.1@1090.88,641.15 R6.1@1133.88,641.15
NetR7_1: R7.1 R8.2 U3.6 | length 71.3
  Bottom Layer w12: R8.2@1002.1,759.83 R7.1@1035.7,759.83 1035.7,757.86 1039.7,753.86 U3.6@1039.7,723.83
NetR9_1: R9.1 R11.1 U4.24 | length 1204
  L5 SIG w5: v1(81.89,836.12) 142.5,836.12 179.96,873.58 857.24,873.58 960.83,770 1131.23,770 v1(1141.4,759.83)
  Bottom Layer w8: v1(81.89,836.12) 81.89,838.09 87.73,843.93 88.74,843.93 103.07,858.26 117.42,858.26 130.21,871.05 U4.24@130.21,888.94
NetR12_1: R12.1 R14.2 U4.22 | length 92.7
  Bottom Layer w8: R14.2@149.89,836.12 R12.1@183.89,836.12 183.89,860.44 170.5,873.83 170.5,888.02 U4.22@169.58,888.94
NetR13_2: R13.2 U4.23 | length 68.1
  Bottom Layer w8: R13.2@115.89,836.12 115.89,838.09 121.73,843.93 123.7,843.93 149.9,870.13 U4.23@149.9,888.94
NetR16_1: R16.1 R23.1 R26.1 U6.3 U8.3 | length 871.9
  Top Layer w8: v1(539.22,1132.05) U8.3@562.41,1132.05 ; v1(539.3,1532.05) U6.3@562.48,1532.05
  Bottom Layer w5: R23.1@361.48,836.12 422.94,836.12 541.95,955.13 R26.1@541.95,1129.32 ; v1(539.22,1132.05) 541.26,1132.05 548.61,1139.39 548.61,1141.43 561.38,1154.2 561.38,1205.1 544.14,1222.33 544.14,1527.2 v1(539.3,1532.05)
  Bottom Layer w8: v1(539.3,1532.05) ccw(c539.3,1533.36) R16.1@540.61,1533.36
NetR19_1: R19.1 R20.2 U6.5 | length 206.8
  Top Layer w8: v1(562.41,1487.68) U6.5@562.41,1492.68
  Bottom Layer w8: v1(562.41,1487.68) 581.13,1487.68 612.83,1519.38 612.83,1520.55 619.35,1527.08 619.35,1540.67 631.55,1552.86 633.21,1552.86 671.45,1591.1 v1@712.72,1591.1
  other v1: 709.12,1591.1
NetR21_1: R21.1 R22.2
NetR28_1: R28.1 R29.2 U8.5 | length 206.8
  Top Layer w8: v1(562.41,1087.68) U8.5@562.41,1092.68
  Bottom Layer w8: v1(562.41,1087.68) 581.13,1087.68 612.83,1119.38 612.83,1120.55 619.35,1127.08 619.35,1140.67 631.55,1152.86 633.21,1152.86 671.45,1191.1 v1@712.72,1191.1
  other v1: 709.12,1191.1
NetR30_1: R30.1 R31.2
NetR32_1: R32.1 U9.12 | length 50
  Bottom Layer w5: U9.12@1223.78,1977.82 R32.1@1223.78,2027.82
NetR33_1: R33.1 U9.1 | length 50
  Bottom Layer w5: U9.1@1334.01,1977.82 R33.1@1334.01,2027.82
NetR36_1: R36.1 U11.16 | length 55
  Top Layer w8: R36.1@415,2070.17 U11.16@470,2070.17
NetR39_1: R39.1 U11.26 | length 65.9
  Top Layer w5: U11.26@719.02,1998.32 v1(719.02,2048.32)
  Bottom Layer w5: v1(719.02,2048.32) R39.1@719.02,2064.17
NetR40_1: R40.1 U10.6 | length 50.1
  Bottom Layer w5: U10.6@738.7,2142.22 738.7,2120.72 758.39,2101.04 R40.1@758.39,2100.25
NetR41_1: R41.1 U11.14 | length 60.1
  Top Layer w12: R41.1@410,2109.22 437.2,2109.22 437.52,2109.54 U11.14@470,2109.54
NetR43_2: R43.2 U11.7 | length 103.5
  Top Layer w8: R43.2@369.53,2254.74 381.34,2254.74 388.74,2247.34 U11.7@470,2247.34
NetR44_2: R44.2 U11.8 | length 103.5
  Top Layer w8: R44.2@369.53,2220.25 381.34,2220.25 388.74,2227.65 U11.8@470,2227.65
NetR46_2: R46.2 U11.6 | length 95.5
  Top Layer w8: v1@510,2267.02 U11.6@470,2267.02 470.73,2266.29 508.02,2266.29 511.29,2263.02 v1(514,2263.02)
  Bottom Layer w8: R46.2@510,2267.02 512,2265.02 R46.2@512,2257.98
NetR47_1: R47.1 U11.62 U12.2 | length 216.5
  Top Layer w8: U11.62@581.22,2437.3 581.67,2437.75 581.67,2472.75 v1(596.22,2487.3)
  Bottom Layer w8: U12.2@582.21,2333.95 582.21,2473.28 588.41,2479.49 590.38,2479.49 596.22,2485.33 v1(596.22,2487.3)
NetR48_1: R48.1 R50.1 U12.4 | length 84.6
  Bottom Layer w8: U12.4@633.39,2333.95 633.39,2375.6 637.48,2379.69 637.48,2381.65 643.32,2387.5 R48.1@670.29,2387.5
NetR49_1: R49.1 U11.63 U12.1 | length 205.4
  Top Layer w8: U11.63@561.54,2437.3 v1(561.54,2487.3)
  Bottom Layer w8: U12.1@556.61,2333.95 556.61,2482.38 v1(561.54,2487.3)
NetR50_2: R50.2 U11.61 U12.3 | length 106.2
  Top Layer w8: U11.61@600.91,2437.3 600.91,2395.21 605.92,2390.2 v1(605.92,2387.5)
  Bottom Layer w8: v1(605.92,2387.5) 607.8,2385.62 U12.3@607.8,2333.95
NetR51_1: R51.1 SW2.2 | length 60
  Bottom Layer w12: SW2.2@107.48,1915 R51.1@167.48,1915
NetR55_2: R55.2 U14.11 U16.1 | length 310.6
  L5 SIG w5: v1(1109.53,2192.04) 1109.53,2189.88 1151.02,2148.39 1160.53,2148.39 1175.59,2133.34 1285.79,2133.34 1316.83,2102.29 1329.42,2102.29 v1(1350,2081.71)
  Bottom Layer w5: U14.11@1099.53,2192.04 v1(1109.53,2192.04)
  Bottom Layer w8: U16.1@1350,2065.97 v1@1350,2079.15
NetR57_1: R57.1 U16.4 | length 47.4
  Bottom Layer w5: U16.4@1310.63,2124.23 1310.63,2131.52 1315.96,2136.85 1317.13,2136.85 1337.95,2157.67 R57.1@1337.95,2159.64
NetR62_1: R62.1 R63.2 | length 551.9
  Top Layer w9.7: R63.2@1483.16,1508.05 1741.08,1508.05 cw(c1741.08,1408.05) 1811.79,1478.76 1854.39,1436.16 cw(c1784.95,1366.72) 1883.16,1366.72 R62.1@1883.16,1288.62
NetR67_2: R67.2 R68.1 | length 551.9
  Top Layer w9.7: R67.2@1483.16,958.05 1741.08,958.05 ccw(c1741.08,1058.05) 1811.79,987.34 1854.39,1029.94 ccw(c1784.95,1099.38) 1883.16,1099.38 R68.1@1883.16,1177.48
NetR69_1: R69.1 R73.2 U18.3 | length 67.1
  Top Layer w9.7: U18.3@2901.95,937.74 2901.95,925.93 2906.95,920.93 R69.1@2906.95,902.74 R73.2@2906.95,872.74
NetR75_1: R75.1 SW3.2 | length 75
  Bottom Layer w5.2: SW3.2@2948.45,98.72 R75.1@3023.45,98.72
NetR78_2: R78.2 R79.1 R80.2 R81.2 | length 88.7
  Top Layer w9.7: R78.2@2076.93,994.26 R80.2@2104.93,994.26 R81.2@2104.93,1017.26 2104.93,1020.04 cw(c2127.15,1020.04) R79.1@2127.15,1042.26
NetR82_1: R82.1 R83.2 R86.2 R87.1 | length 88.7
  Top Layer w9.7: R87.1@2149.75,1042.26 cw(c2149.75,1020.04) 2171.97,1020.04 R82.1@2171.97,1017.26 R83.2@2171.97,994.26 R86.2@2199.97,994.26
NetR90_2: R90.2 R91.1 R92.2 R93.2 | length 88.7
  Top Layer w9.7: R91.1@2149.75,1455.33 ccw(c2149.75,1477.56) 2171.97,1477.56 2171.97,1480.33 R92.2@2171.97,1503.33 R90.2@2199.97,1503.33
NetR94_1: R94.1 R95.2 R98.2 R99.1 | length 88.7
  Top Layer w9.7: R98.2@2076.93,1503.33 R95.2@2104.93,1503.33 2104.93,1480.33 2104.93,1477.56 ccw(c2127.15,1477.56) R99.1@2127.15,1455.33
NetR120_2: R120.2 U1.1 | length 50
  Top Layer w8: v1(2041.2,1319.66) U1.1@2091.2,1319.66
NetR121_2: R121.2 U1.9 | length 108.2
  Top Layer w5: v1(2021.2,1146.93) 2019.8,1146.93 2018.69,1148.05 2018.8,1148.05 2026.06,1155.3 2026.06,1155.41 2041.2,1170.56 2041.2,1176.93 2057.95,1193.68 U1.9@2091.2,1193.68
  Bottom Layer w8: R121.2@2021.2,1136.93 v1(2021.2,1146.93)
NetR123_2: R123.2 U19.1 | length 43.5
  Bottom Layer w12: U19.1@1526.21,627.87 R123.2@1526.21,671.34
NetR124_2: R124.2 SW4.1 U20.2 | length 113.2
  Bottom Layer w12: U20.2@1520.3,408.64 1554.43,408.64 1566.22,396.85 1566.22,335.65 v1(1567.09,334.78)
NetR126_2: R126.2 U1.35 | length 40.6
  Top Layer w5: U1.35@2193.56,1343.29 2193.56,1355.7 2194.32,1356.45 2194.32,1375.45 2193.56,1376.2 R126.2@2193.56,1383.29
NetR127_2: R127.2 U1.10 | length 30.4
  Top Layer w5: v1(2071.2,1176.93) 2072.2,1177.93 U1.10@2091.2,1177.93
  Bottom Layer w5: R127.2@2071.2,1166.93 v1(2071.2,1176.93)
NetR128_2: R128.2 U19.3 | length 43.5
  Bottom Layer w12: U19.3@1601.01,627.87 R128.2@1601.01,671.34
NetR129_2: R129.2 U1.16 | length 40.6
  Top Layer w5: R129.2@2193.56,1114.31 2193.56,1121.4 2194.32,1122.15 2194.32,1141.14 2193.56,1141.9 U1.16@2193.56,1154.31
NetR130_1: R130.1 SW5.1 | length 42.4
  Bottom Layer w12: v1(1654.13,1743.53) R130.1@1684.13,1713.53
NetR131_1: R131.1 U21.3 | length 42.3
  Bottom Layer w14: R131.1@1886.62,1647.03 U21.3@1916.5,1617.16
NetR133_2: R133.2 SW5.2 | length 42.4
  Bottom Layer w12: v1(1689.48,1778.88) R133.2@1719.48,1748.88
NetR136_2: R136.2 U22.3 | length 37.1
  Top Layer w10: U22.3@3319.06,264.36 3333.82,264.36 3338.82,269.36 R136.2@3354.06,269.36
NetR149_1: R149.1 U23.4 | length 35
  Bottom Layer w5: R149.1@1034.92,2365.12 U23.4@1034.92,2400.12
NetSW2_1: SW2.1 U13.1 U13.5 U15.15 | length 2362
  Top Layer w5: v1(1208.98,2284.23) 1173.35,2284.23 1154.53,2303.05 1154.53,2324.34 ; v1(1208.98,2362.97) 1171.86,2362.97 1154.53,2345.64 1154.53,2324.34 ; v1(1299.02,2154.64) 1269.38,2154.64 1237.25,2122.52 1186.32,2122.52 1181.19,2117.39 1134.92,2117.39 1088.67,2163.64 1038.73,2163.64 992.48,2209.89 992.48,2242.28 966.29,2268.47 966.29,2314.4 976.23,2324.34 1154.53,2324.34
  L5 SIG w5: SW2.1@107.48,1815 340,1815 566.72,2041.72 566.72,2188.52 713.83,2335.63 713.83,2337.27 781.12,2404.56 1001.89,2404.56 1122.22,2284.23 v1(1208.98,2284.23)
  Bottom Layer w5: v1(1208.98,2362.97) U13.5@1228.98,2362.97 ; U15.15@1274.02,2154.64 v1(1299.02,2154.64)
NetSW3_1: SW3.1 U17.9 | length 1249.3
  Top Layer w5.2: SW3.1@2848.45,98.72 2848.45,260.29 2680,428.74 2680,1022.84 2808.28,1151.13 U17.9@2882.27,1151.13
NetU1_27: U1.27
NetU17_1: U17.1 U18.7 | length 50
  Top Layer w9.7: U18.7@2882.27,1047.98 2882.27,1059.79 U17.1@2882.27,1097.98
NetU17_2: U17.2 U18.6 | length 50
  Top Layer w9.7: U18.6@2901.95,1047.98 U17.2@2901.95,1097.98
NetU19_4: U19.4 U20.4 | length 94.7
  Bottom Layer w12: U19.4@1601.01,525.51 cw(c1601.01,519.61) 1606.92,519.61 U20.4@1606.92,434.23
PDN/SYNC: J12.3 R142.1 | length 841.1
  Top Layer w5: v1(3302.95,1305) R142.1@3312.95,1305
  L5 SIG w5: J12.3@2672.25,1788.88 2819.08,1788.88 v1(3302.95,1305)
PG-C2M: J1.D1 R138.2 | length 50
  Top Layer w12: R138.2@3622.44,2360 3623.23,2360 3648.81,2334.42 3660.27,2334.42 v1(3661.42,2333.27)
PG-M2C: J1.F1 R138.1 | length 50
  Top Layer w12: v1(3561.42,2333.27) 3562.57,2334.42 3574.02,2334.42 3599.61,2360 R138.1@3600.39,2360
PRSNT-M2C-L: J1.H2 R146.2 | length 5.3
  Top Layer w10: R146.2@3461.42,2277.95 v1(3461.42,2283.27)
RESET: C81.2 PP10.1 R121.1 R122.1 R123.1 R125.2 R128.1 | length 838.1
  Bottom Layer w5: R128.1@1601.01,710.71 R128.1@1601.01,712.68 ; R125.2@1638.32,710.8 1638.32,827.67 1882.91,1072.26 1942.44,1072.26 1985.06,1114.88 R121.1@2021.2,1114.88
  Bottom Layer w12: PP10.1@1458.21,710.71 R123.1@1526.21,710.71 C81.2@1563.61,710.71 ; R128.1@1601.01,710.71 C81.2@1563.61,710.71 ; 1628.38,710.71 C81.2@1563.61,710.71 ; R125.2@1628.47,710.8 R125.2@1638.32,710.8
SCL_I2C: PP6.1 U9.14 U13.6 U22.6 | length 6133.9
  Top Layer w5: v1(3147.87,225) 3168.23,245.35 ; 3168.23,245.57 3168.23,245.35 ; U22.6@3201.8,264.36 3174.82,264.36 3168.23,257.77 3168.23,245.35
  L5 SIG w5: v1(1269.05,2013.41) 1266.57,2010.92 1266.57,2003.87 1265.87,2003.17 1265.87,1986.58 1246.61,1967.32 1224.4,1967.32 1199.09,1992.63 1032.58,1992.63 986.08,2039.13 986.08,2217.17 1014.43,2245.51 1266.78,2245.51 1318.35,2297.08 1318.35,2329.47 PP6.1@1351.85,2362.97 1351.85,2443.99 1525.94,2618.09 3315.56,2618.09 3539.7,2393.95 3539.7,1119.7 3628.21,1031.19 3628.21,827.47 3553.52,752.78 3303.53,752.78 3220.91,670.17 3220.91,308.82 3199.85,287.76 3199.85,255.56 3169.29,225 v1(3147.87,225)
  Bottom Layer w5: U13.6@1261.85,2362.97 PP6.1@1351.85,2362.97
SCL_Local: J1.C30 R140.2
  other v1: 3711.42,883.27
SCLK_DUT: PP7.1 R126.1 U15.2 | length 1984.8
  Top Layer w5: v1(1234.65,2106.02) 1254.59,2125.97 PP7.1@1385,2125.97 ; R126.1@2193.56,1405.33 v1(2193.56,1415.33)
  L5 SIG w5: v1(1498.58,2098.63) 1518.8,2098.63 1695.96,1921.47 1695.96,1825.49 1802.59,1718.87 1939.67,1718.87 1949.59,1708.94 1990.32,1708.94 2004.43,1723.05 2254.88,1723.05 2284.68,1693.25 2359.14,1693.25 2391.31,1661.08 v1(2455.46,1661.08)
  Bottom Layer w5: v1(1234.65,2106.02) U15.2@1234.65,2131.02 ; PP7.1@1385,2125.97 1471.24,2125.97 v1(1498.58,2098.63) ; v1(2193.56,1415.33) 2178.12,1415.33 2152.3,1441.16 2152.3,1465.05 2201.51,1514.26 2308.64,1514.26 v1(2455.46,1661.08)
SDA_I2C: PP5.1 U9.13 U13.10 U22.5 | length 5729.3
  Top Layer w5: v1(3147.87,264.37) 3167.55,284.05 ; U22.5@3201.8,284.05 3168.23,284.05 ; 3167.55,284.05 3168.23,284.05 ; 3167.55,284.05 3168.23,284.05
  L5 SIG w5: v1(1249.37,1993.41) 1087.29,2155.49 1087.29,2201.16 1108.93,2222.79 1329.99,2222.79 1348.2,2241 1348.2,2280.58 PP5.1@1351.85,2284.23 1351.85,2309.78 1385,2342.93 1385,2446.97 1546.11,2608.09 3311.42,2608.09 3528.65,2390.86 3528.65,1107.02 3590.66,1045 3590.66,810.66 3545.25,765.24 3259.96,765.24 3147.87,653.16 v1(3147.87,264.37)
  Bottom Layer w5: U13.10@1261.85,2284.23 PP5.1@1351.85,2284.23
SDA_Local: J1.C31 R141.2
  other v1: 3711.42,833.27
SDIO_DUT: PP9.1 R127.1 U15.7 | length 1759.6
  Top Layer w5: v1(1154.53,2165.39) 1202.18,2213.04 1218.07,2213.04 1219.95,2214.92 1356.05,2214.92 PP9.1@1385,2185.97
  Bottom Layer w5: v1(1154.53,2165.39) 1157.23,2165.39 1162.23,2170.39 U15.7@1179.53,2170.39 ; PP9.1@1385,2185.97 1392.55,2185.97 1433.53,2144.99 1522.19,2144.99 1574.47,2092.72 1574.47,1550.75 1626.54,1498.67 1626.54,1470.95 1837.61,1259.88 1837.61,1233.17 1859.03,1211.75 1997.21,1211.75 2011.68,1197.28 2011.68,1193.42 2053.49,1151.6 2065.27,1151.6 2071.2,1145.67 R127.1@2071.2,1144.88
SEN_DUT: PP8.1 R129.1 U15.5 | length 2122.3
  Top Layer w5: v1(1154.53,2133.89) 1157.02,2136.38 1157.02,2144.54 1203.61,2191.14 1275.68,2191.14 1292.18,2174.64 1302.35,2174.64 1320.99,2156 1413.04,2156 1426.4,2169.36 1426.4,2204.56 PP8.1@1385,2245.97 ; v1(2193.56,1082.26) R129.1@2193.56,1092.26
  Bottom Layer w5: v1(1154.53,2133.89) 1157.23,2133.89 1162.23,2138.89 U15.5@1179.53,2138.89 ; PP8.1@1385,2245.97 1449.66,2245.97 1602.43,2093.19 1602.43,1569.45 1684.54,1487.34 1684.54,1463.02 1784.28,1363.29 1784.28,1361.98 1919.33,1226.93 2118.71,1226.93 2135.43,1210.22 2135.43,1190.34 2133.12,1188.03 2133.12,1131.01 2152.3,1111.84 2179.36,1111.84 2193.56,1097.63 v1(2193.56,1082.26)
SMA_CLK_N: C52.2 J5.1 R67.1 | length 200
  Top Layer w9.7: J5.1@1261.11,958.05 C52.2@1461.11,958.05
SMA_CLK_P: J4.1 R63.1 | length 200
  Top Layer w9.7: J4.1@1261.11,1508.05 R63.1@1461.11,1508.05
TDI_FMC: J1.D30 R139.2 | length 13.3
  Top Layer w10: R139.2@3661.42,869.98 v1(3661.42,883.27)
TDO_FMC: J1.D31 R139.1 | length 14.7
  Top Layer w10: v1(3661.42,833.27) R139.1@3661.42,847.93
USB_5V: D6.1 R42.2 | length 72.4
  Bottom Layer w18: R42.2@218.64,2024.59 255.06,2024.59 v1(280.47,2050)
USB_I2C_SCL: R34.1 R39.2 U10.7 | length 56
  Bottom Layer w5: R39.2@719.02,2086.22 719.02,2093.3 R34.1@719.02,2106.22 719.02,2116.06 U10.7@719.02,2142.22
USB_I2C_SDAr: R38.2 R40.2 U11.28 U13.9 | length 804.4
  Top Layer w5: U11.28@758.39,1998.32 758.39,2034.35 v1(784.92,2060.88)
  L5 SIG w5: v1(784.92,2060.88) 882.7,2060.88 921.46,2099.64 921.46,2179.39 999.16,2257.09 1233.54,2257.09 1280.35,2303.91 v1(1301.85,2303.91)
  Bottom Layer w5: R40.2@758.39,2060.88 v1(784.92,2060.88) ; U13.9@1261.85,2303.91 v1(1301.85,2303.91)
USB_I2C_SDAw: R37.1 U10.1 U11.27 | length 320.3
  Top Layer w5: v1(699.33,2211.86) 738.7,2172.49 U11.27@738.7,1998.32
  Bottom Layer w5: v1(699.33,2211.86) U10.1@699.33,2264.27 R37.1@699.33,2302.27
VADJ: J1.E39 J1.F40 J1.G39 J1.H40 | length 212.1
  Bottom Layer w5: J1.H40@3461.42,383.27 J1.G39@3511.42,433.27 J1.F40@3561.42,383.27 J1.E39@3611.42,433.27
VCM: C61.2 C69.2 C79.2 C80.2 R81.1 R82.2 R93.1 R94.2 TP3.1 U1.8 | length 42.1
  Top Layer w5: v1(2071.2,1210.43) 2072.2,1209.43 U1.8@2091.2,1209.43
  Bottom Layer w9: C79.2@2060.77,1210.43 v1(2071.2,1210.43) C80.2@2082.49,1210.43
  other v1: 2138.45,999.26 2138.45,1496.94
VCORE: C35.2 U11.12 U11.37 U11.49 U11.64 | length 92.5
  Top Layer w5: v1(873.98,2148.91) U11.37@908.5,2148.91
  Top Layer w12: U11.12@470,2148.91 v1(520,2148.91)
  Bottom Layer w12: v1@512,2148.91 v1(520,2148.91)
  other v1: 531.85,2417.3 855,2436.85 531.85,2437.3 531.85,2457.3
VREF: C83.2 C84.2 C85.2 J13.2 R132.2 U1.2 | length 60.4
  Top Layer w8: C85.2@2062.2,1298.92 v1(2066.2,1298.92) cw(c2078.27,1286.84) 2078.27,1303.92 U1.2@2091.2,1303.92
  Bottom Layer w14: v1(2066.2,1298.92) 2071.2,1303.92 C84.2@2071.2,1326.92
  other v1: 2072.72,1374.15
